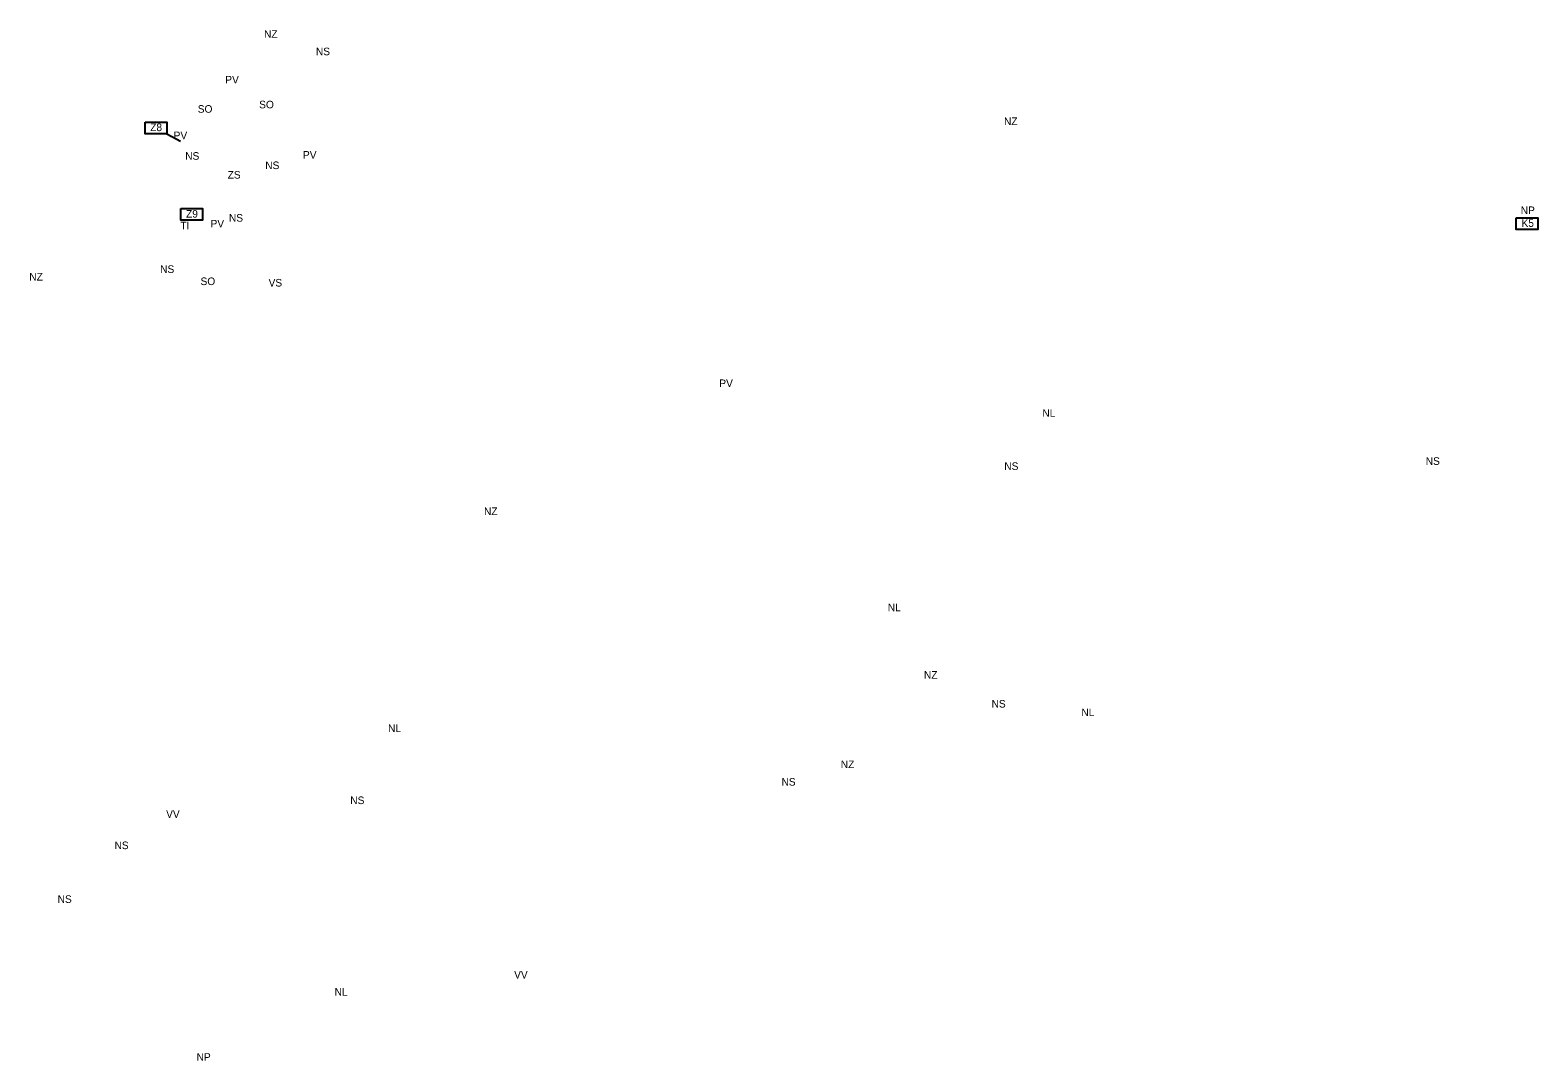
# Model space of a CAD drawing. Extents: x -547343 to -529607, y -1096298 to -1087453.
# Drawn here: x -543010 to -541025, y -1094749 to -1093392 of the extents above; entities that cross this region are included whole.
import ezdxf

# ---------------------------------------------------------------- set-up
doc = ezdxf.new("R2010")
doc.units = 0
for name, color, linetype in [('Vrstva 10', 7, 'Continuous'), ('Vrstva 11', 7, 'Continuous'), ('Vrstva 59', 7, 'Continuous'), ('Vrstva 60', 7, 'Continuous')]:
    doc.layers.add(name, color=color, linetype=linetype)

msp = doc.modelspace()

# ---------------------------------------------------------------- linework, layer by layer
at = {"layer": 'Vrstva 59'}
msp.add_line((-542830.2, -1093528.9), (-542812.2, -1093538.5), dxfattribs=at)
for points in [[(-542858.9, -1093513.4), (-542830.2, -1093513.4), (-542830.2, -1093528.9), (-542858.9, -1093528.9)], [(-542811.7, -1093627.3), (-542783.1, -1093627.3), (-542783.1, -1093642.8), (-542811.7, -1093642.8)]]:
    msp.add_lwpolyline(points, close=True, dxfattribs=at)
at = {"layer": 'Vrstva 60'}
msp.add_lwpolyline([(-541053.3, -1093639.5), (-541024.7, -1093639.5), (-541024.7, -1093655), (-541053.3, -1093655)], close=True, dxfattribs=at)

# ---------------------------------------------------------------- texts
at = {"layer": 'Vrstva 10'}
for s, p in [('NZ', (-542702.2, -1093402.5)), ('NS', (-542633.9, -1093425.5)), ('PV', (-542753.2, -1093462.7)), ('SO', (-542789.5, -1093501.2)), ('SO', (-542708.6, -1093495.4)), ('NZ', (-541727.7, -1093517.4)), ('NS', (-542806, -1093563.1)), ('PV', (-542650.9, -1093561.7)), ('NS', (-542700.6, -1093575.4)), ('ZS', (-542750.1, -1093587.9)), ('PV', (-542772.6, -1093652.2)), ('NS', (-542748.4, -1093644.6)), ('NZ', (-543011.3, -1093722.1)), ('NS', (-542839, -1093712.1)), ('SO', (-542785.8, -1093728.1)), ('VS', (-542696.2, -1093730)), ('PV', (-542102.6, -1093862.4)), ('NL', (-541677.2, -1093901.5)), ('NS', (-541727.3, -1093971.5)), ('NS', (-541172.3, -1093964.8)), ('NZ', (-542412.5, -1094030.9)), ('NL', (-541880.7, -1094157.6)), ('NZ', (-541833.1, -1094246.3)), ('NS', (-541744.1, -1094284.3)), ('NL', (-541625.8, -1094295.6)), ('NL', (-542538.8, -1094316.6)), ('NZ', (-541942.6, -1094364.1)), ('NS', (-542020.7, -1094387.1)), ('NS', (-542588.6, -1094411.4)), ('VV', (-542831.1, -1094429.6)), ('NS', (-542899.1, -1094470.7)), ('NS', (-542974, -1094541.5)), ('VV', (-542372.8, -1094641.1)), ('NL', (-542609.2, -1094663.7)), ('NP', (-542791, -1094749.4))]:
    msp.add_text(s, height=10, dxfattribs=at).set_placement(p)
at = {"layer": 'Vrstva 11'}
for s, p in [('PV', (-542821.2, -1093536.1)), ('NP', (-541047.2, -1093634.6)), ('TI', (-542812.5, -1093654.6))]:
    msp.add_text(s, height=10, dxfattribs=at).set_placement(p)
at = {"layer": 'Vrstva 59'}
for s, p in [('Z8', (-542852.1, -1093525.4)), ('Z9', (-542804.9, -1093639.3))]:
    msp.add_text(s, height=10, dxfattribs=at).set_placement(p)
at = {"layer": 'Vrstva 60'}
msp.add_text('K5', height=10, dxfattribs=at).set_placement((-541046.2, -1093651.5))

doc.saveas('drawing.dxf')
